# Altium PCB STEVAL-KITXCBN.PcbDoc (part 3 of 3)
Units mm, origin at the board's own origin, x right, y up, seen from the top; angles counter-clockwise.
Board outline 110 x 100 mm, 4 copper layers (Top Layer, GND, PWR, Bottom Layer), stack 1.53 mm thick; 227 components, 137 nets, 699 pads, 698 vias.
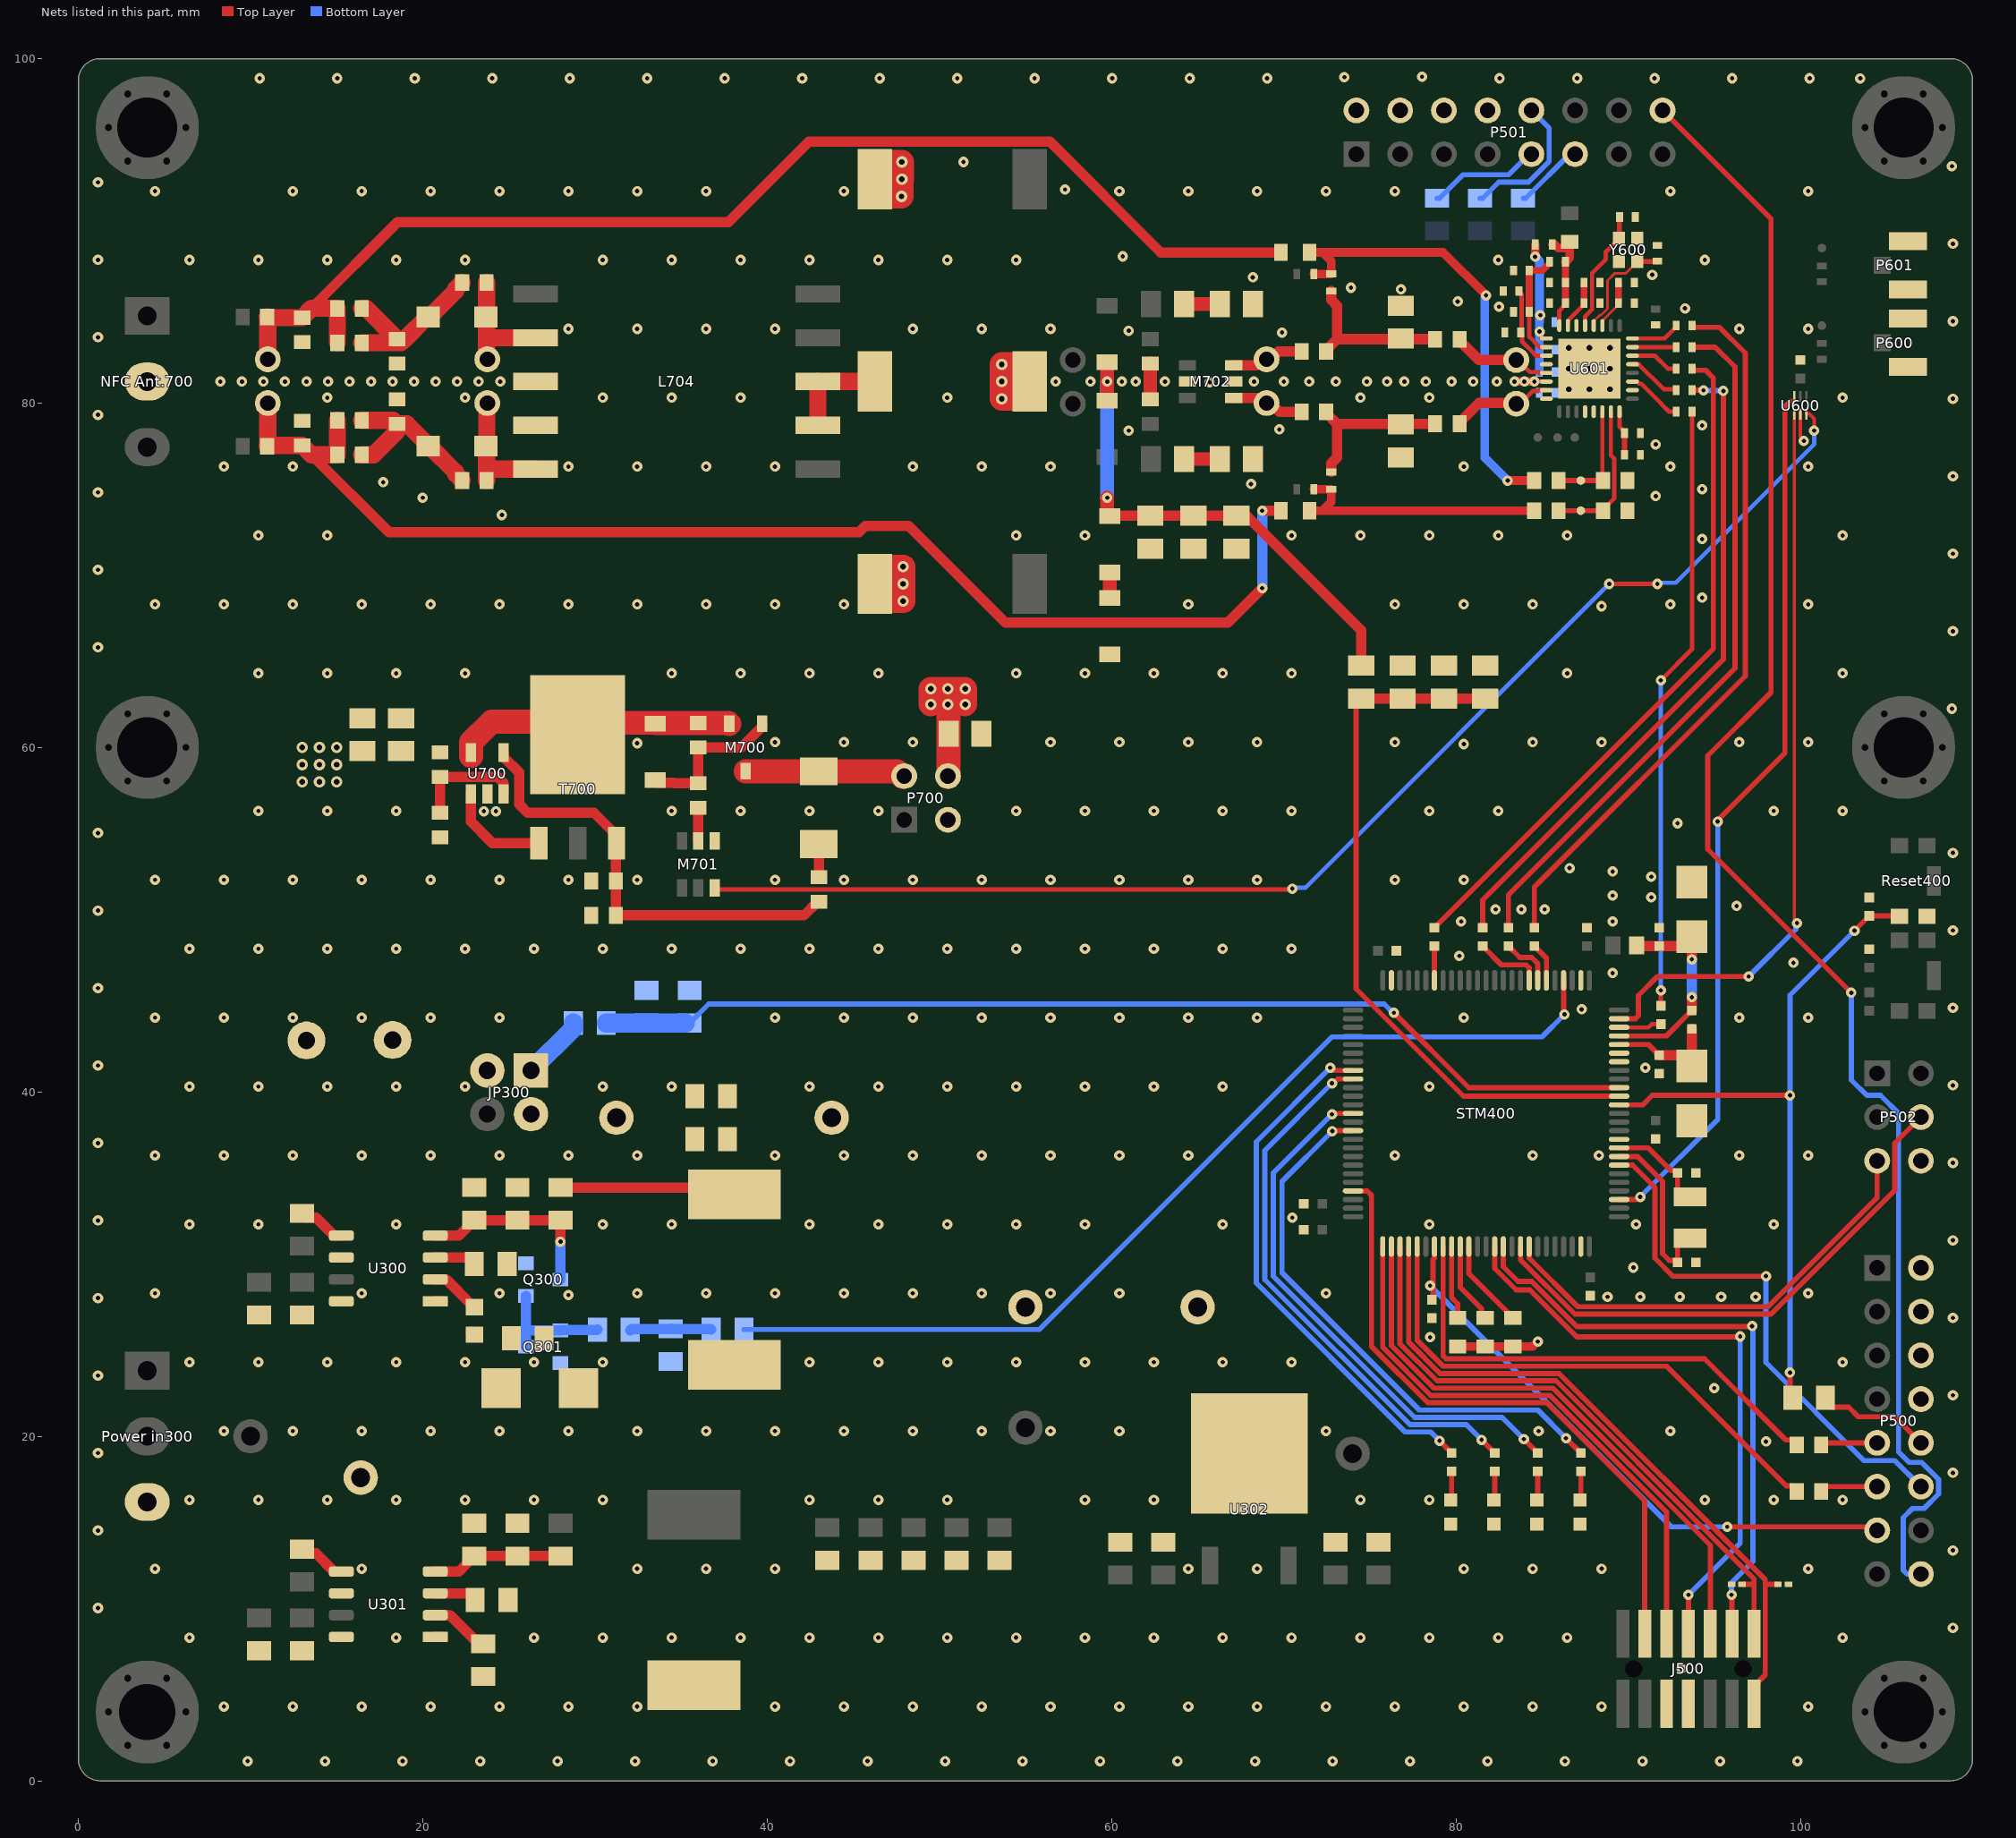
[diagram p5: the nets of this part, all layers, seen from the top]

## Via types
v1: diameter 0.6, hole 0.25, Top Layer to Bottom Layer, 566 vias
v2: diameter 0.66, hole 0.33, Top Layer to Bottom Layer, 94 vias
v3: diameter 0.6, hole 0.25, Top Layer to Bottom Layer, tented both sides, 38 vias

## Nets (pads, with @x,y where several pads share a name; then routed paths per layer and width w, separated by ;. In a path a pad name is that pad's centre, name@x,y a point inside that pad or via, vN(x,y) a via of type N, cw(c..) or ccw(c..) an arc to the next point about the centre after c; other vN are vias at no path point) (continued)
GND: "NFC Ant.700.2" "Power in300.3" C300.2 C301.1 C303.1 C304.1 C305.1 C306.1 C307.2 C308.2 C309.2 C311.2 C312.1 C313.2 C314.1 C315.1 C316.1 C317.1 C318.1 C319.2 C320.1 C321.2 C322.2 C323.1 C400.2 C402.2 C403.1 C404.2 C405.2 C406.2 C407.2 C408.1 C409.1 C410.1 C411.1 C412.1 C413.1 C600.1 C601.2 C602.2 C603.1 C608.2 C609.2 C610.2 C611.2 C612.2 C613.2 C618.2 C619.2 C620.2 C621.2 C622.2 C623.2 C624.2 C625.2 C626.2 C627.2 C628.2 C629.2 C700.2 C701.2 C702.2 C703.2 C704.2 C707.2 C708.1 C709.2 C710.2 C712.2 C713.2 C714.1 C715.1 D500.A D501.A D705.2 J400.1 J401.1 J402.1 J500.5 J500.7 L704.8 L704.9 LD401.1 LD402.1 LD403.1 LD404.1 M701.4 M702.2 M702.5 P500.2 P500.4 P500.6 P500.8 P501.2 P501.4 P501.6 P501.8 P502.6 P600.2 P600.3 P601.2 P601.3 Q300.2 Q301.2 R301.1 R305.1 R309.1 R400.1 R401.1 R610.2 R611.1 R705.2 R706.2 R707.2 R708.2 R711.2 Reset400.1 STM400.10 STM400.19 STM400.20 STM400.27 STM400.49 STM400.99 TP300.1 TP301.1 TP302.1 TP303.1 U300.6 U300.8 U301.6 U301.8 U302.2 U600.2 U601.6 U601.12 U601.16 U601.20 U601.21 U601.26 U601.33 U700.2 Y600.2 Y600.4 | length 6.6
  Top Layer w0.2: U600.2@100,79.53 100,78.081 100.2,77.881 v1(100.2,77.8)
  Top Layer w0.5: J400.1@80.1,25.218 J401.1@81.7,25.218 J402.1@83.3,25.218 84.468,25.218 v1(84.75,25.5)
  other v1: 9.832,1.143 14.332,1.143 18.832,1.143 23.332,1.143 27.832,1.143 32.332,1.143 36.832,1.143 41.332,1.143 45.832,1.143 50.332,1.143 54.832,1.143 59.332,1.143 63.832,1.143 68.332,1.143 72.832,1.143 77.332,1.143 81.832,1.143 86.332,1.143 90.832,1.143 95.332,1.143 99.832,1.143 8.456,4.31 12.456,4.31 16.456,4.31 20.456,4.31 24.456,4.31 28.456,4.31 32.456,4.31 40.456,4.31 44.456,4.31 48.456,4.31 52.456,4.31 56.456,4.31 60.456,4.31 64.456,4.31 68.456,4.31 72.456,4.31 76.456,4.31 80.456,4.31 84.456,4.31 88.456,4.31 100.456,4.31 93.1,6.5 6.456,8.31 18.456,8.31 26.456,8.31 30.456,8.31 34.456,8.31 38.456,8.31 42.456,8.31 46.456,8.31 50.456,8.31 54.456,8.31 58.456,8.31 62.456,8.31 66.456,8.31 70.456,8.31 74.456,8.31 78.456,8.31 82.456,8.31 86.456,8.31 102.456,8.31 108.857,8.88 1.143,10.031 4.456,12.31 16.456,12.31 32.456,12.31 36.456,12.31 40.456,12.31 64.456,12.31 68.456,12.31 80.456,12.31 84.456,12.31 88.456,12.31 100.456,12.31 108.857,13.38 1.143,14.531 6.456,16.31 10.456,16.31 14.456,16.31 18.456,16.31 22.456,16.31 26.456,16.31 30.456,16.31 42.456,16.31 46.456,16.31 50.456,16.31 58.456,16.31 62.456,16.31 74.456,16.31 78.456,16.31 94.456,16.31 98.456,16.31 102.456,16.31 108.857,17.88 1.143,19.031 98,19.7 8.456,20.31 12.456,20.31 16.456,20.31 20.456,20.31 24.456,20.31 28.456,20.31 32.456,20.31 36.456,20.31 40.456,20.31 44.456,20.31 48.456,20.31 52.456,20.31 56.456,20.31 60.456,20.31 72.456,20.31 84.8,20.31 92.456,20.31 108.857,22.38 95,22.8 1.143,23.531 6.456,24.31 10.456,24.31 14.456,24.31 18.456,24.31 22.456,24.31 26.456,24.31 30.456,24.31 42.456,24.31 46.456,24.31 50.456,24.31 54.456,24.31 58.456,24.31 62.456,24.31 66.456,24.31 70.456,24.31 102.456,24.31 78.5,25.75 108.857,26.88 1.143,28.031 88.8,28.1 90.7,28.1 93,28.1 95.4,28.1 97.4,28.1 28.456,28.2 4.456,28.31 16.456,28.31 24.456,28.31 32.456,28.31 36.456,28.31 40.456,28.31 44.456,28.31 48.456,28.31 52.456,28.31 56.456,28.31 60.456,28.31 72.456,28.31 100.456,28.31 90.3,29.8 108.857,31.38 6.456,32.31 10.456,32.31 18.456,32.31 30.456,32.31 34.456,32.31 42.456,32.31 46.456,32.31 50.456,32.31 54.456,32.31 58.456,32.31 66.456,32.31 78.456,32.31 90.456,32.31 98.456,32.31 1.143,32.531 70.5,32.7 108.857,35.88 4.456,36.31 8.456,36.31 12.456,36.31 16.456,36.31 20.456,36.31 24.456,36.31 28.456,36.31 32.456,36.31 40.456,36.31 44.456,36.31 48.456,36.31 52.456,36.31 56.456,36.31 60.456,36.31 64.456,36.31 76.456,36.31 84.456,36.31 88.3,36.31 96.456,36.31 100.456,36.31 1.143,37.031 6.456,40.31 10.456,40.31 14.456,40.31 18.456,40.31 22.456,40.31 30.456,40.31 34.456,40.31 42.456,40.31 46.456,40.31 50.456,40.31 54.456,40.31 58.456,40.31 62.456,40.31 66.456,40.31 78.456,40.31 108.857,40.38 91,41.4 1.143,41.531 4.456,44.31 8.456,44.31 12.456,44.31 16.456,44.31 20.456,44.31 24.456,44.31 40.456,44.31 44.456,44.31 48.456,44.31 52.456,44.31 56.456,44.31 60.456,44.31 64.456,44.31 68.456,44.31 80.456,44.31 96.456,44.31 100.456,44.31 87.3,44.8 108.857,44.88 1.143,46.031 89.1,46.9 99.6,47.5 80.2,47.9 6.456,48.31 10.456,48.31 14.456,48.31 18.456,48.31 22.456,48.31 26.456,48.31 30.456,48.31 34.456,48.31 38.456,48.31 42.456,48.31 46.456,48.31 50.456,48.31 54.456,48.31 58.456,48.31 62.456,48.31 66.456,48.31 70.456,48.31 108.857,49.38 80.3,49.9 89.1,49.9 1.143,50.531 82.3,50.6 83.8,50.6 85.15,50.6 96.3,50.8 91.34,51.3 89.1,51.4 4.456,52.31 8.456,52.31 12.456,52.31 16.456,52.31 20.456,52.31 24.456,52.31 28.456,52.31 32.456,52.31 40.456,52.31 44.456,52.31 48.456,52.31 52.456,52.31 56.456,52.31 60.456,52.31 64.456,52.31 68.456,52.31 76.456,52.31 80.456,52.31 91.34,52.5 89.1,52.8 86.6,53 108.857,53.88 1.143,55.031 92.871,55.601 23.55,56.3 24.25,56.3 10.456,56.31 14.456,56.31 18.456,56.31 34.456,56.31 38.456,56.31 42.456,56.31 46.456,56.31 54.456,56.31 58.456,56.31 62.456,56.31 66.456,56.31 70.456,56.31 78.456,56.31 82.456,56.31 98.456,56.31 102.456,56.31 80.456,60.2 32.456,60.25 40.456,60.31 44.456,60.31 48.456,60.31 56.456,60.31 60.456,60.31 64.456,60.31 68.456,60.31 76.456,60.31 84.456,60.31 88.456,60.31 96.456,60.31 100.456,60.31 108.799,62.251 10.456,64.31 14.456,64.31 18.456,64.31 22.456,64.31 34.456,64.31 38.456,64.31 42.456,64.31 46.456,64.31 54.456,64.31 58.456,64.31 62.456,64.31 66.456,64.31 70.456,64.31 86.456,64.31 102.456,64.31 1.143,65.817 108.857,66.751 88.456,68.2 4.456,68.31 8.456,68.31 12.456,68.31 16.456,68.31 20.456,68.31 24.456,68.31 28.456,68.31 32.456,68.31 36.456,68.31 40.456,68.31 44.456,68.31 64.456,68.31 76.456,68.31 80.456,68.31 84.456,68.31 92.456,68.31 100.456,68.31 94.3,68.7 1.143,70.317 108.857,71.251 94.3,72.1 10.456,72.31 14.456,72.31 54.456,72.31 58.456,72.31 70.456,72.31 74.456,72.31 78.456,72.31 82.456,72.31 86.456,72.31 102.456,72.31 24.6,73.5 20,74.5 91.6,74.6 1.143,74.817 94.3,75 68.1,75.3 17.7,75.4 108.857,75.751 8.456,76.31 12.456,76.31 28.456,76.31 32.456,76.31 36.456,76.31 40.456,76.31 48.456,76.31 52.456,76.31 56.456,76.31 80.456,76.31 92.456,76.31 100.456,76.31 91.6,77.6 69.741,78.471 94.3,78.7 1.143,79.317 108.857,80.251 14.456,80.31 22.456,80.31 30.456,80.31 34.456,80.31 38.456,80.31 50.456,80.31 74.456,80.31 78.456,80.31 102.456,80.31 65.7,81.2 1.143,83.817 69.9,84.1 28.456,84.31 32.456,84.31 36.456,84.31 40.456,84.31 48.456,84.31 52.456,84.31 56.456,84.31 96.456,84.31 100.456,84.31 108.857,84.751 93.3,85.5 82.5,85.6 80.1,85.9 76.8,86.6 73.9,86.7 68.2,87.3 91.4,87.45 1.143,88.317 6.456,88.31 10.456,88.31 14.456,88.31 18.456,88.31 22.456,88.31 30.456,88.31 34.456,88.31 38.456,88.31 42.456,88.31 46.456,88.31 50.456,88.31 54.456,88.31 82.456,88.31 94.456,88.31 60.654,88.518 108.857,89.251 4.456,92.31 12.456,92.31 16.456,92.31 20.456,92.31 24.456,92.31 28.456,92.31 32.456,92.31 36.456,92.31 44.456,92.31 60.456,92.31 64.456,92.31 68.456,92.31 72.456,92.31 76.456,92.31 92.456,92.31 100.456,92.31 57.3,92.4 1.143,92.817 108.799,93.751 51.4,94 10.537,98.857 15.037,98.857 19.537,98.857 24.037,98.857 28.537,98.857 33.037,98.857 37.537,98.857 42.037,98.857 46.537,98.857 51.037,98.857 55.537,98.857 60.037,98.857 64.537,98.857 69.037,98.857 82.537,98.857 87.037,98.857 91.537,98.857 96.037,98.857 100.537,98.857 103.473,98.854 73.52,98.919 78.037,98.945
  other v2: 86.55,80.8 87.75,80.8 88.95,80.8 86.55,82 87.75,82 88.95,82 86.55,83.2 87.75,83.2 88.95,83.2
  other v3: 61,78.4 8.25,81.25 9.5,81.25 10.75,81.25 12,81.25 13.25,81.25 14.5,81.25 15.75,81.25 17,81.25 18.25,81.25 19.5,81.25 20.75,81.25 22,81.25 23.25,81.25 24.5,81.25 56.75,81.25 58.775,81.25 60.6,81.25 61.4,81.25 63.1,81.25 68.275,81.25 70,81.25 71.475,81.25 73.025,81.25 74.825,81.25 76,81.25 77,81.25 78.25,81.25 79.75,81.25 81,81.25 82.375,81.25 61,84.2
IGBT_drive: P500.16 P501.16 | length 97.7
  Top Layer w0.3: P501.16@92,96.995 98.3,90.695 98.3,63.199 94.625,59.524 94.625,54.094 v1(102.959,45.759)
  Bottom Layer w0.3: v1(102.959,45.759) 102.959,40.692 103.852,39.799 104.65,39.799 105.7,38.75 105.7,19.1 106.313,18.487 107.042,18.487 108.025,17.505 108.025,16.655 107.18,15.81 106.51,15.81 105.975,15.275 105.975,12.225 106.2,12 P500.16@107,12
INTR: R402.1 R603.2 | length 35.2
  Top Layer w0.25: R402.1@91.9,45 v1(91.9,45.9) ; v1(91.9,63.9) 93.707,65.707 R603.2@93.707,79.5
  Bottom Layer w0.25: v1(91.9,45.9) v1(91.9,63.9)
LED1: R411.1 STM400.58 | length 31.1
  Top Layer w0.3: v1(72.7,41.4) 72.781,41.4 72.931,41.25 STM400.58@74.025,41.25 ; v1(79.042,19.742) R411.1@79.75,19.033
  Bottom Layer w0.3: v1(72.7,41.4) 68.4,37.1 68.4,28.9 77.05,20.25 78.533,20.25 v1(79.042,19.742)
LED2: R408.1 STM400.59 | length 31.9
  Top Layer w0.3: v1(72.8,40.5) 72.881,40.5 73.131,40.75 STM400.59@74.025,40.75 ; v1(81.492,19.792) R408.1@82.25,19.033
  Bottom Layer w0.3: v1(72.8,40.5) 68.9,36.6 68.9,29.1 77.325,20.675 80.608,20.675 v1(81.492,19.792)
LED3: R407.1 STM400.63 | length 31.7
  Top Layer w0.3: v1(72.8,38.7) 72.85,38.75 STM400.63@74.025,38.75 ; v1(83.942,19.842) R407.1@84.75,19.033
  Bottom Layer w0.3: v1(72.8,38.7) 69.4,35.3 69.4,29.297 77.597,21.1 82.683,21.1 v1(83.942,19.842)
LED4: R406.1 STM400.65 | length 32.3
  Top Layer w0.3: v1(72.819,37.719) 72.85,37.75 STM400.65@74.025,37.75 ; v1(86.392,19.892) R406.1@87.25,19.033
  Bottom Layer w0.3: v1(72.819,37.719) 69.9,34.8 69.9,29.5 77.875,21.525 84.758,21.525 v1(86.392,19.892)
MISO: R403.1 R607.2 | length 42.2
  Top Layer w0.3: R403.1@84.55,49.533 84.55,51.897 96.8,64.147 96.8,82.9 95.3,84.4 93.757,84.4 93.707,84.45 R607.2@93.707,84.5
MOSI: R404.1 R606.2 | length 41
  Top Layer w0.3: R404.1@83.05,49.533 83.05,51.448 96.2,64.598 96.2,82.1 95.05,83.25 R606.2@93.707,83.25
NetC302_1: C302.1 U300.2 | length 2.9
  Top Layer w0.6: U300.2@20.725,29.115 21.36,29.115 22.8,27.675 22.825,27.675 C302.1@23,27.5
NetC302_2: C302.2 D300.1 R310.2 U300.1 | length 0.7
  Top Layer w0.6: U300.1@20.725,27.845 U300.1@21.15,27.845 ; C302.2@22.8,26.075 22.825,26.075 C302.2@23,25.9
NetC307_1: C307.1 U300.3 | length 2.5
  Top Layer w0.6: U300.3@20.725,30.385 22.75,30.385 23,30.135 C307.1@23,30
NetC308_1: C308.1 Q300.3 R303.1 R305.2 U300.4 | length 11.2
  Top Layer w0.6: U300.4@20.725,31.655 22.105,31.655 22.6,32.15 22.6,32.3 22.85,32.55 C308.1@23,32.55 R305.2@25.5,32.55 R303.1@28,32.55 v1(28,31.3)
  Bottom Layer w0.6: Q300.3@28,29.1 v1(28,31.3)
NetC309_1: C309.1 R304.2 R306.2 | length 4.8
  Bottom Layer w0.6: R306.2@32.05,26.15 32.125,26.225 34.375,26.225 C309.1@34.4,26.25 34.425,26.225 36.725,26.225 R304.2@36.75,26.2
NetC310_1: C310.1 L301.1 U301.1 | length 0.4
  Top Layer w0.6: U301.1@20.725,8.345 U301.1@21.15,8.345
NetC310_2: C310.2 U301.2 | length 3.5
  Top Layer w0.6: U301.2@20.725,9.615 21.485,9.615 21.5,9.6 21.6,9.6 23,8.2 23.25,8.2 C310.2@23.5,7.95
NetC313_1: C313.1 U301.3 | length 2.5
  Top Layer w0.5: C313.1@22.75,10.885 23.05,10.585 C313.1@23.05,10.5
  Top Layer w0.6: U301.3@20.725,10.885 C313.1@22.75,10.885
NetC319_1: C319.1 R308.1 R309.2 U301.4 | length 7.9
  Top Layer w0.6: U301.4@20.725,12.155 22.105,12.155 22.6,12.65 22.6,12.8 C319.1@22.85,13.05 ; C319.1@23,13.05 C319.1@22.85,13.05 ; R308.1@28,13.05 R309.2@25.5,13.05 C319.1@22.85,13.05
NetC601_1: C601.1 C602.1 U601.24 | length 2.6
  Top Layer w0.25: U601.24@89.5,79.5 89.5,78.622 89.793,78.329 C601.1@89.793,78.25
  Top Layer w0.3: C602.1@89.793,77 C601.1@89.793,78.25
NetC604_2: C604.2 J602.2 J603.1 J604.2 | length 15.4
  Top Layer w0.5: J603.1@71.5,73.75 72.25,73.75 ; J602.2@71.75,75 72.175,75 ; 72.225,75 J604.2@72.75,75 72.75,74.25 72.25,73.75 ; C604.2@84.539,73.75 72.25,73.75
NetC605_2: C605.2 J604.1 R602.1 R610.1 | length 9.6
  Top Layer w0.6: R602.1@72.461,79.5 72.461,79.424 73.096,78.789 ; J604.1@72.75,76 72.75,76.501 73.096,76.847 73.096,78.789 ; C605.2@78.789,78.789 73.096,78.789
NetC616_2: C616.2 J607.2 R608.1 R611.2 | length 9.6
  Top Layer w0.6: R608.1@72.461,83 72.461,83.076 73.096,83.711 ; J607.2@72.75,86.5 72.75,85.999 73.096,85.653 73.096,83.711 ; C616.2@78.789,83.711 73.096,83.711
NetC617_1: C617.1 J607.1 J608.2 J609.1 | length 26.6
  Top Layer w0.5: J609.1@71.5,88.75 72.25,88.75 ; J608.2@71.75,87.5 72.475,87.5 J607.1@72.75,87.5 72.75,88.25 72.25,88.75 ; v1(81.75,86.25) 79.25,88.75 72.25,88.75 ; v1(83,75.5) C617.1@84.539,75.5
  Bottom Layer w0.5: v1(81.75,86.25) 81.75,86.223 81.675,86.148 81.675,76.825 v1(83,75.5)
NetC628_1: C628.1 U601.4 Y600.3 | length 6.4
  Top Layer w0.15: U601.4@88,84.5 88,84.75 88.37,85.12 88.439,85.12 88.799,85.48 88.799,87.119 89.203,87.522 89.847,87.522 90.525,88.2 Y600.3@90.525,88.225
  Top Layer w0.2: U601.4@88,84.5 U601.4@88.01,84.51
  Top Layer w0.3: Y600.3@90.525,88.225 C628.1@91.603,88.225
  Top Layer w0.4: C628.1@91.621,88.243 C628.1@91.7,88.243
NetC629_1: C629.1 U601.5 Y600.1 | length 7.1
  Top Layer w0.25: U601.5@87.5,84.5 87.5,85.024 87.907,85.431 87.907,87.554 88.7,88.347 88.7,88.777 89.473,89.55 Y600.1@89.473,89.575 Y600.1@89.487,89.588 ; C629.1@89.487,90.787 C629.1@89.5,90.8
  Top Layer w0.3: Y600.1@89.487,89.588 C629.1@89.487,90.787
NetC700_1: C700.1 L700.2 L701.2 L702.2 P700.4 | length 26.1
  Top Layer w1.4: L700.2@46.25,69.5 46.25,70.2 46.55,70.5 v2(47.9,70.5) v2(47.9,69.5) v2(47.9,68.5) L700.2@46.55,68.5 ; L701.2@46.55,92.7 L701.2@46.25,93 46.25,92.3 46.55,92 v2(47.8,92) 47.8,92.975 v2(47.825,93) v2(47.825,94) L701.2@46.575,94 ; v2(49.5,62.5) v2(49.5,63.4) v2(50.5,63.4) v2(51.5,63.4) v2(51.5,62.5) ; P700.4@50.54,58.3 v2@50.54,62.5 ; L702.2@54.975,80.25 v2(53.625,80.25) v2(53.625,81.25) v2(53.625,82.25) L702.2@54.975,82.25 ; L702.2@55.25,80.5 L702.2@55.25,81.25 L702.2@55.25,82
  other v2: 50.5,62.5
NetC705_2: C705.2 C706.1 | length 2.1
  Top Layer w0.8: C706.1@62.25,80.211 C705.2@62.25,82.289
NetC707_1: C707.1 R703.2 R707.1 R708.1 STM400.15 | length 41.9
  Top Layer w0.3: R703.2@74.2,62.847 74.2,45.987 80.437,39.75 STM400.15@89.475,39.75
  Top Layer w0.6: R703.2@74.5,62.847 R707.1@76.9,62.847 C707.1@79.3,62.847 R708.1@81.7,62.847
NetC708_2: C708.2 R704.2 R711.1 T700.3 U700.4 | length 26.5
  Top Layer w0.6: U700.4@24.7,59.7 24.7,59.45 25.6,58.55 25.6,56.7 26.1,56.2 29.95,56.2 31.25,54.9 T700.3@31.25,54.45 31.211,54.411 C708.2@31.211,52.25 R711.1@31.211,50.25 42.135,50.25 42.924,51.039 R704.2@43,51.039
NetC709_1: C709.1 R709.2 | length 2.1
  Top Layer w0.8: R709.2@64.203,85.75 C709.1@66.298,85.75
NetC710_1: C710.1 R710.2 | length 2.1
  Top Layer w0.8: R710.2@64.203,76.75 C710.1@66.298,76.75
NetC711_1: C711.1 C712.1 L703.2 R712.2 R713.1 | length 10.5
  Top Layer w1: R713.1@16.461,77 17.15,77 18.5,78.35 C712.1@18.5,78.789 ; C711.1@16.461,79 16.464,78.997 18.291,78.997 C712.1@18.5,78.789 ; R712.2@22.289,75.5 21.914,75.875 21.914,75.986 20.4,77.5 20.25,77.5 20.15,77.6 20.15,77.722 19.083,78.789 C712.1@18.5,78.789
NetC714_2: C714.2 C716.1 L705.2 R716.2 R717.1 | length 10.6
  Top Layer w1: C716.1@16.461,83.5 18.75,83.5 C714.2@18.961,83.711 ; R717.1@16.461,85.5 16.711,85.5 C714.2@18.5,83.711 C714.2@18.961,83.711 ; R716.2@22.289,87 21.914,86.625 21.914,86.514 20.4,85 L705.2@20.325,85 20.25,85 C714.2@18.961,83.711
NetD300_2: D300.2 L300.1 R310.1
NetD700_2: D700.2 M700.1 R701.2 R702.1 | length 9
  Top Layer w0.6: D700.2@33.5,58.115 33.655,57.96 34.58,57.96 34.617,57.922 R702.1@36,57.922 R701.2@36,60 38.5,60 39.7,61.2 M700.1@39.7,61.375
NetD701_1: D701.1 R704.1 | length 1.9
  Top Layer w0.6: R704.1@43,52.461 D701.1@43,54.39
NetD701_2: D701.2 M700.3 P700.2 | length 9.2
  Top Layer w1.4: M700.3@38.75,58.625 47.535,58.625 P700.2@47.86,58.3
NetD704_2: D704.2 D705.1 | length 1.5
  Top Layer w0.8: D705.1@59.9,68.685 D704.2@59.9,70.165
NetJ701_1: J701.1 L703.1 L704.10 R712.1 | length 7.4
  Top Layer w1: R712.1@23.711,75.5 23.711,76.2 ; J701.1@23.75,80 23.713,79.962 23.713,77.538 L703.1@23.675,77.5 23.711,77.464 23.711,76.2 ; L704.10@26.55,76.17 23.741,76.17 23.711,76.2
NetJ701_2: J701.2 L704.7 L705.1 R716.1 | length 7.3
  Top Layer w1: R716.1@23.711,87 23.711,83.8 ; J701.2@23.75,82.54 23.711,82.579 23.711,83.8 ; L704.7@26.55,83.79 23.721,83.79 23.711,83.8
NetLD401_2: LD401.2 R411.2 | length 1.8
  Top Layer w0.3: LD401.2@79.75,16.198 R411.2@79.75,17.967
NetLD402_2: LD402.2 R408.2 | length 1.8
  Top Layer w0.3: LD402.2@82.25,16.198 R408.2@82.25,17.967
NetLD403_2: LD403.2 R407.2 | length 1.8
  Top Layer w0.3: LD403.2@84.75,16.198 R407.2@84.75,17.967
NetLD404_2: LD404.2 R406.2 | length 1.8
  Top Layer w0.3: LD404.2@87.25,16.198 R406.2@87.25,17.967
NetM701_1: M701.5 R702.2 | length 1.9
  Top Layer w0.6: M701.5@36,54.576 R702.2@36,56.5
NetP500_9: P500.9 R500.2 | length 3.1
  Top Layer w0.3: R500.2@101.45,19.5 101.57,19.62 P500.9@104.46,19.62
NetP500_10: P500.10 R501.1 | length 6.7
  Top Layer w0.3: R501.1@101.45,22.25 101.45,22.1 101.85,21.7 102.8,21.7 103.365,21.135 105.485,21.135 P500.10@107,19.62
NetP500_11: P500.11 R502.2 | length 3.4
  Top Layer w0.3: R502.2@101.211,16.8 101.211,16.824 101.468,17.08 P500.11@104.46,17.08
NetP501_9: P501.9 R503.2 | length 6.5
  Bottom Layer w0.3: R503.2@78.9,91.9 79.05,91.9 80.413,93.263 83.062,93.263 84.254,94.455 P501.9@84.38,94.455
NetP501_10: P501.10 R504.1 | length 8.3
  Bottom Layer w0.3: R504.1@81.4,91.9 81.55,91.9 82.488,92.838 83.199,92.838 84.212,92.838 85.405,94.03 85.405,95.97 84.496,96.879 P501.10@84.38,96.995
NetP501_11: P501.11 R505.2 | length 4.2
  Bottom Layer w0.3: R505.2@83.9,91.9 84.05,91.9 86.605,94.455 P501.11@86.92,94.455 ; P501.11@86.875,94.34 P501.11@87.035,94.34
NetQ300_1: Q300.1 Q301.1 Q301.3 R306.1 | length 7.1
  Bottom Layer w0.6: Q301.3@26,25.2 26,26.2 ; Q300.1@26,28.15 26,26.2 ; R306.1@30.15,26.2 30.125,26.175 28.025,26.175 Q301.1@28,26.15 26.05,26.15 26,26.2
NetR302_1: R302.1 U300.5 | length 2.8
  Top Layer w0.6: R302.1@13,32.95 13.25,32.7 13.805,32.7 14.85,31.655 U300.5@15.275,31.655
NetR307_1: R307.1 U301.5 | length 2.8
  Top Layer w0.5: U301.5@14.85,12.155 U301.5@15.275,12.155
  Top Layer w0.6: R307.1@13,13.45 13.25,13.2 13.805,13.2 U301.5@14.85,12.155
NetR402_2: R402.2 STM400.23 | length 2.5
  Top Layer w0.25: STM400.23@89.475,43.75 89.485,43.74 91.174,43.74 91.367,43.933 R402.2@91.9,43.933
NetR403_2: R403.2 STM400.31 | length 2.3
  Top Layer w0.3: R403.2@84.55,48.467 85.25,47.767 STM400.31@85.25,46.475
NetR404_2: R404.2 STM400.32 | length 3.1
  Top Layer w0.3: R404.2@83.05,48.467 83.709,47.807 84.393,47.807 84.75,47.45 STM400.32@84.75,46.475
NetR405_2: R405.2 STM400.33 | length 4
  Top Layer w0.3: R405.2@81.55,48.467 82.634,47.382 84.074,47.382 84.25,47.206 STM400.33@84.25,46.475
NetR410_2: R410.2 STM400.44 | length 2
  Top Layer w0.3: STM400.44@78.75,46.475 R410.2@78.75,48.467
NetR603_1: R603.1 U601.27 | length 3.3
  Top Layer w0.25: U601.27@90.25,81.25 90.5,81.25 90.625,81.125 90.753,81.125 91.95,79.928 91.95,79.916 92.364,79.502 92.718,79.502 92.719,79.5 R603.1@92.793,79.5
NetR604_1: R604.1 U601.29 | length 3.2
  Top Layer w0.25: U601.29@90.25,82.25 90.616,82.25 92.061,80.805 92.738,80.805 R604.1@92.793,80.75
NetR605_1: R605.1 U601.30 | length 2.9
  Top Layer w0.25: U601.30@90.25,82.75 91.55,82.75 92.3,82 R605.1@92.793,82
NetR606_1: R606.1 U601.31 | length 2.5
  Top Layer w0.25: U601.31@90.25,83.25 R606.1@92.793,83.25
NetR607_1: R607.1 U601.32 | length 2.9
  Top Layer w0.25: U601.32@90.25,83.75 92.122,83.75 92.793,84.421 R607.1@92.793,84.5
NetR700_2: R700.2 R706.1 U700.3 | length 6.6
  Top Layer w0.6: R706.1@21,56.211 R700.2@21,58.289 24.349,58.289 24.7,57.937 U700.3@24.7,57.3
NetSTM400_3: STM400.3 U600.6 | length 51.4
  Top Layer w0.2: 99.4,80.1 99.65,80.1 U600.6@99.65,80.2
  Top Layer w0.3: STM400.3@89.475,33.75 90.469,33.75 90.619,33.9 v1(90.7,33.9) ; v1(95.2,55.7) 95.2,55.781 99.1,59.681 99.1,79.8 99.4,80.1
  Bottom Layer w0.3: v1(90.7,33.9) 95.2,38.4 v1(95.2,55.7)
NetSTM400_24: STM400.24 U600.1 | length 43.3
  Top Layer w0.2: U600.1@99.65,79.53 99.65,50.058 99.8,49.908 v1(99.8,49.8)
  Top Layer w0.3: STM400.24@89.475,44.25 90.424,44.25 90.6,44.426 90.6,45.6 91.7,46.7 v1(97,46.7)
  Bottom Layer w0.3: v1(97,46.7) 99.743,49.443 99.743,49.743 v1(99.8,49.8)
NetT700_1: T700.1 U700.1 | length 6.1
  Top Layer w0.6: U700.1@22.8,57.3 22.8,55.7 24.05,54.45 T700.1@26.75,54.45
NFC_Ready: P500.13 R401.2 STM400.82 | length 35.2
  Top Layer w0.3: v1(78.5,28.75) v1@78.675,28.75 ; R401.2@78.6,27.933 78.675,28.008 v1@78.675,28.75 ; STM400.82@78.75,31.025 78.75,30.35 78.675,30.275 v1@78.675,28.75 ; v1(95.75,14.75) 104.25,14.75 P500.13@104.46,14.54
  Bottom Layer w0.3: v1(78.5,28.75) 92.5,14.75 v1(95.75,14.75)
NFC_Reset: C403.2 R501.2 Reset400.2 STM400.14 | length 41.7
  Top Layer w0.3: STM400.14@89.475,39.25 90.85,39.25 91.4,39.8 v1(99.4,39.8) ; R501.2@99.3,22.4 99.4,22.5 v1(99.4,23.7) ; v1(103.142,49.358) C403.2@104,50.217 105.733,50.217 Reset400.2@105.75,50.2
  Bottom Layer w0.3: v1(99.4,23.7) v1(99.4,39.8) 99.4,45.617 v1(103.142,49.358)
NFC_Uart_Rx: R500.1 STM400.83 | length 29
  Top Layer w0.3: STM400.83@79.25,31.025 79.25,24.676 79.426,24.5 94.438,24.5 99.151,19.787 99.532,19.787 99.789,19.531 R500.1@99.789,19.5
NFC_Uart_Tx: R502.1 STM400.80 | length 31.1
  Top Layer w0.3: STM400.80@77.75,31.025 77.75,25.575 79.25,24.075 92.225,24.075 99.182,17.118 99.532,17.118 99.55,17.101 R502.1@99.55,16.75
NFC_Wake_Up: P500.12 STM400.7 | length 30.6
  Top Layer w0.3: STM400.7@89.475,35.75 90.25,35.75 91.551,34.449 91.551,30.349 92.6,29.3 v1(98,29.3)
  Bottom Layer w0.3: v1(98,29.3) 98,24.287 103.692,18.595 105.485,18.595 P500.12@107,17.08
PA1: J606.2 M702.3 R608.2 | length 4.3
  Top Layer w0.6: M702.3@67.1,82.2 68.416,82.2 68.756,82.54 J606.2@69,82.54 69.244,82.54 69.704,83 R608.2@71.039,83
PA2: J606.1 M702.1 R602.2 | length 4.3
  Top Layer w0.6: M702.1@67.1,80.3 68.456,80.3 68.756,80 J606.1@69,80 69.244,80 69.744,79.5 R602.2@71.039,79.5
PC14: C400.1 STM400.8 X400.2 | length 10.3
  Top Layer w0.3: STM400.8@89.475,36.25 90.55,36.25 92,34.8 92,30.6 92.386,30.214 92.752,30.214 C400.1@92.867,30.1 92.867,31.1 93.267,31.5 X400.2@93.6,31.5
PC15: C402.1 STM400.9 X400.1 | length 5.9
  Top Layer w0.3: STM400.9@89.475,36.75 91.169,36.75 92.489,35.429 92.737,35.429 C402.1@92.867,35.3 92.867,34.3 93.267,33.9 X400.1@93.6,33.9
RFI1: C617.2 C625.1 TP601.1 U601.22 | length 6.6
  Top Layer w0.25: U601.22@88.5,79.5 88.5,75.539 C625.1@88.539,75.5
  Top Layer w0.3: C617.2@85.961,75.5 TP601.1@87.25,75.5 C625.1@88.539,75.5
RFI1_E: C715.2 C716.2 J609.2 J702.2 R715.1 R717.2 | length 71.7
  Top Layer w0.6: 13.539,85.5 18.539,90.5 37.75,90.5 42.425,95.175 56.426,95.175 62.851,88.75 J609.2@69.836,88.75
  Top Layer w1: R715.1@10.961,85 R715.1@11,84.961 ; J702.2@11,82.54 R715.1@11,84.961 ; C716.2@15.039,83.5 R717.2@15.039,85.5 13.539,85.5 C715.2@13,84.961 R715.1@11,84.961
RFI2: C603.2 C604.1 TP600.1 U601.23 | length 8.7
  Top Layer w0.25: C603.2@88.539,73.75 88.539,73.826 89.195,74.483 89.195,76.769 89,76.964 U601.23@89,79.5
  Top Layer w0.3: C604.1@85.961,73.75 TP600.1@87.25,73.75 C603.2@88.539,73.75
RFI2_E: C711.2 C713.1 J603.2 J702.1 R713.2 R714.1 | length 74.8
  Top Layer w0.6: 13.539,77 18.039,72.5 45.338,72.5 45.713,72.875 48.208,72.875 53.833,67.25 66.75,67.25 v1(68.75,69.25) ; v1(68.75,73.75) J603.2@69.836,73.75
  Top Layer w1: R714.1@10.961,77.5 R714.1@11,77.539 ; J702.1@11,80 R714.1@11,77.539 ; C711.2@15.039,79 R713.2@15.039,77 13.539,77 C713.1@13,77.539 R714.1@11,77.539
  Bottom Layer w0.6: v1(68.75,69.25) v1(68.75,73.75)
RFO1: C616.1 J605.2 U601.13 | length 6
  Top Layer w0.25: J605.2@83.5,82.5 83.591,82.5 84.291,81.8 84.778,81.8 84.828,81.75 U601.13@85.241,81.75
  Top Layer w0.6: C616.1@80.211,83.776 C616.1@80.211,83.7 80.211,83.624 81.335,82.5 83.453,82.5 83.476,82.524 J605.2@83.5,82.5
RFO2: C605.1 J605.1 U601.15 | length 6
  Top Layer w0.25: J605.1@83.5,79.96 83.736,79.96 84.476,80.7 84.778,80.7 84.828,80.75 U601.15@85.25,80.75
  Top Layer w0.6: C605.1@80.211,78.624 C605.1@80.211,78.7 ; C605.1@80.211,78.8 80.211,78.876 81.335,80 83.4,80 83.47,79.93 J605.1@83.5,79.96
SCLK: R410.1 R605.2 | length 40.1
  Top Layer w0.3: R410.1@78.75,49.533 94.95,65.733 94.95,81.45 94.5,81.9 93.757,81.9 93.707,81.95 R605.2@93.707,82
SEN: R405.1 R604.2 | length 38.8
  Top Layer w0.3: R405.1@81.55,49.533 81.55,51.15 95.525,65.125 v1(95.525,80.7) ; R604.2@93.707,80.75 93.713,80.744 94.369,80.744 v1(94.375,80.737)
  Bottom Layer w0.3: v1(94.375,80.737) 94.394,80.719 95.506,80.719 v1(95.525,80.7)
Spare_GPIO: P502.5 STM400.93 | length 26.8
  Top Layer w0.3: STM400.93@84.25,31.025 84.25,30.349 87.074,27.525 98.126,27.525 104.46,33.859 P502.5@104.46,36
Spare_PWM: P502.4 STM400.92 | length 31.4
  Top Layer w0.3: STM400.92@83.75,31.025 83.75,30.248 86.898,27.1 98.302,27.1 105.485,34.283 105.485,37.025 106.811,38.351 P502.4@106.85,38.351
STLINK_UART_RX: D500.K J500.13 STM400.79 | length 40.2
  Top Layer w0.3: STM400.79@77.25,31.025 77.25,25.474 79.074,23.65 85.985,23.65 97.96,11.675 97.96,10.9 97.96,6.14 97.31,5.49 J500.13@97.31,4.465 ; 97.96,11.4 D500.K@98.7,11.4
STLINK_UART_TX: D501.K J500.14 STM400.78 | length 35.7
  Top Layer w0.3: STM400.78@76.75,31.025 76.75,25.373 78.898,23.225 85.809,23.225 95.195,13.839 97.31,11.724 97.31,10.9 J500.14@97.31,8.535 ; D501.K@96.7,11.4 97.31,11.4
SYS_JTCK_SWDCLK: J500.6 STM400.76 | length 32.2
  Top Layer w0.3: STM400.76@75.75,31.025 75.75,25.171 78.546,22.375 85.457,22.375 92.23,15.602 J500.6@92.23,9.67
SYS_JTDI: J500.10 STM400.77 | length 34.2
  Top Layer w0.3: STM400.77@76.25,31.025 76.25,25.272 78.722,22.8 85.633,22.8 94.77,13.663 J500.10@94.77,8.535
SYS_JTDO_SWO: J500.8 STM400.89 | length 35.7
  Top Layer w0.3: STM400.89@82.25,31.025 82.25,29.749 83.499,28.5 84.296,28.5 87.021,25.775 96.475,25.775 v1(96.5,25.8) ; J500.8@93.5,8.535 v1(93.5,10.8)
  Bottom Layer w0.3: v1(93.5,10.8) 96.5,13.8 v1(96.5,25.8)
SYS_JTMS_SWDIO: J500.4 STM400.72 | length 37.3
  Top Layer w0.3: STM400.72@74.025,34.25 74.85,34.25 75.1,34 75.1,25.219 78.37,21.95 85.281,21.95 90.96,16.271 J500.4@90.96,8.535
SYS_JTRST: J500.12 STM400.90 | length 34.5
  Top Layer w0.3: STM400.90@82.75,31.025 82.75,29.85 83.6,29 84.397,29 87.022,26.375 97.175,26.375 v1(97.2,26.4) ; v1(96,10.8) 96.02,10.78 96.02,9.68 J500.12@96.1,9.6
  Bottom Layer w0.3: v1(96,10.8) 96,11.5 97.25,12.75 97.25,26.35 v1(97.2,26.4)
TypeB: M701.3 U600.3 | length 76.8
  Top Layer w0.2: U600.3@100.35,79.53 100.35,79.365 100.515,79.365 100.8,79.08 v1(100.8,78.4)
  Top Layer w0.25: M701.3@36.95,51.846 M701.3@36.996,51.8 ; M701.3@36.996,51.75 v1@70.5,51.75 ; v1(88.9,69.5) v1(91.7,69.5)
  Bottom Layer w0.25: v1(70.5,51.8) 70.567,51.867 71.267,51.867 v1(88.9,69.5) ; v1(91.7,69.5) 91.767,69.567 92.767,69.567 100.8,77.6 v1(100.8,78.4)
Ucenter: L702.1 L704.2 L704.3 | length 5
  Top Layer w1: L704.2@42.95,78.71 L704.3@42.95,81.25 ; L704.3@43.75,81.25 L702.1@46.25,81.25
Upeak: C703.1 C704.1 D702.1 D703.1 D704.1 R703.1 R705.1 | length 29.6
  Top Layer w0.6: D704.1@59.9,73.452 C704.1@62.25,73.452 R705.1@64.75,73.452 66.5,73.452 66.552,73.4 67.9,73.4 74.5,66.8 R703.1@74.5,64.752
  Top Layer w0.8: v1(59.75,74.5) 59.75,73.49 59.805,73.435 D704.1@59.9,73.435 ; D703.1@59.75,80.135 v1(59.75,81.25) D702.1@59.75,82.365
  Bottom Layer w0.8: v1(59.75,74.5) v1(59.75,81.25)
V_CNTR: R304.1 STM400.29 | length 57.2
  Top Layer w0.3: STM400.29@86.25,46.475 86.25,44.55 v1(86.3,44.5)
  Bottom Layer w0.3: R304.1@38.65,26.2 55.8,26.2 72.8,43.2 85,43.2 v1(86.3,44.5)
V_POWER: C301.2 R300.1 R301.2 STM400.16 | length 61
  Top Layer w0.3: v1(76.4,44.6) 80.75,40.25 STM400.16@89.475,40.25
  Bottom Layer w0.3: C301.2@35.5,44 36.6,45.1 75.839,45.1 76.339,44.6 v1(76.4,44.6)
  Bottom Layer w1.1: R300.1@30.65,44 R301.2@33,44 C301.2@35.25,44
VDD: C626.1 C627.1 J610.2 J611.1 R609.1 U601.8 | length 5.8
  Top Layer w0.25: U601.8@86,84.5 86,85.363 86.357,85.721 C626.1@86.357,85.8
  Top Layer w0.4: C626.1@86.357,85.8 C627.1@86.357,87 R609.1@86.357,88.2
  Top Layer w0.5: J610.2@85.6,89.2 85.737,89.2 85.945,88.993 86.502,88.993 86.6,88.895 86.6,88.422 86.378,88.2 R609.1@86.357,88.2
VDD_A: C623.1 C624.1 U601.7 | length 2.9
  Top Layer w0.25: U601.7@86.5,84.5 86.5,84.78 86.845,85.125 86.847,85.125 87.443,85.721 C623.1@87.443,85.8
  Top Layer w0.4: C623.1@87.443,85.8 C624.1@87.443,87
VDD_AM: C608.1 C609.1 U601.11 | length 4.8
  Top Layer w0.25: C609.1@83.657,86.5 83.807,86.35 83.807,84.15 C608.1@83.757,84.1 ; C608.1@83.832,84.1 83.832,83.582 84.5,82.914 84.5,82.9 84.65,82.75 U601.11@85.25,82.75
VDD_D: C621.1 C622.1 U601.3 | length 2.8
  Top Layer w0.15: U601.3@88.525,84.803 C621.1@89.443,85.721
  Top Layer w0.2: U601.3@88.5,84.5 U601.3@88.5,84.764 ; C621.1@89.443,85.721 C621.1@89.443,85.8
  Top Layer w0.4: C621.1@89.443,85.8 C622.1@89.443,87
VDD_RF: C610.1 C611.1 C619.1 C620.1 J610.1 U601.9 U601.14 | length 10.1
  Top Layer w0.25: v3(84.55,81.25) U601.14@85.25,81.25 ; v3(84.857,84.15) 84.905,84.102 84.905,83.845 85,83.75 U601.9@85.25,83.75
  Top Layer w0.5: v3(83.4,81.25) v3(83.975,81.25) v3(84.55,81.25) ; v3(84.6,88.5) J610.1@84.6,89.2
  Bottom Layer w0.5: v3(84.6,88.5) 84.85,88.25 84.85,85.15 84.85,84.707 C620.1@84.843,84.7 84.843,84.164 v3(84.857,84.15) 84.843,84.136 C619.1@84.843,83.1 C610.1@84.843,81.8
  other v3: 84.9,85.1
VDD_TX: C612.1 C613.1 R609.2 U601.10 | length 6.4
  Top Layer w0.25: C612.1@84.257,85.3 C612.1@84.332,85.225 ; C612.1@84.332,85.221 84.257,85.146 84.257,83.843 84.85,83.25 U601.10@85.25,83.25 ; R609.2@85.443,88.121 R609.2@85.443,88.2
  Top Layer w0.4: C612.1@84.257,85.3 C613.1@84.257,87.521 ; C613.1@84.257,87.7 85.022,87.7 R609.2@85.443,88.121
VDDA: C405.1 C407.1 L400.1 R409.1 STM400.22 | length 12.6
  Top Layer w0.3: STM400.22@89.475,43.25 92.217,43.25 R409.1@93.7,44.733
  Top Layer w0.6: L400.1@90.486,48.467 C407.1@91.8,48.467 93.154,48.467 C405.1@93.7,49.012 v1(93.7,47.7) ; R409.1@93.7,44.733 v1(93.7,45.5)
  Bottom Layer w0.6: v1(93.7,45.5) v1(93.7,47.7)
Version_GPIO_1: J400.2 STM400.84 | length 4.3
  Top Layer w0.3: STM400.84@79.75,31.025 79.75,28.05 80.1,27.7 J400.2@80.1,26.882
Version_GPIO_2: J401.2 STM400.85 | length 4.7
  Top Layer w0.3: STM400.85@80.25,31.025 80.25,28.65 81.475,27.425 81.475,27.107 J401.2@81.7,26.882
Version_GPIO_3: J402.2 STM400.86 | length 5.2
  Top Layer w0.3: STM400.86@80.75,31.025 80.75,29.446 83.021,27.175 83.032,27.175 83.097,27.11 J402.2@83.356,27.11
Von: C300.1 C701.1 C702.1 D700.1 JP300.1 JP300.3 M700.2 P700.3 R300.2 R700.1 R701.1 T700.4 U700.5 | length 20.6
  Top Layer w1.1: T700.4@28.25,61.5 T700.4@29,60.75
  Top Layer w1.4: U700.5@22.8,59.5 22.8,60.3 24,61.5 T700.4@28.25,61.5 ; T700.4@29,60.75 29.684,61.434 D700.1@33.451,61.434 ; D700.1@33.537,61.422 37.753,61.422 M700.2@37.8,61.375
  Bottom Layer w1.1: JP300.1@26.29,41.25 28.75,43.71 R300.2@28.75,44
  other v2: 13,58 14,58 15,58 13,59 14,59 15,59 13,60 14,60 15,60
VREF+: C404.1 C406.1 R409.2 STM400.21 | length 6.9
  Top Layer w0.3: STM400.21@89.475,42.75 91.183,42.75 C404.1@91.8,42.133
  Top Layer w0.6: C404.1@91.8,42.133 93.111,42.133 C406.1@93.7,41.544 ; C406.1@93.7,41.5 C406.1@93.7,41.544 ; R409.2@93.7,43.667 C406.1@93.7,41.544
Vreg: C303.2 C304.2 JP300.2 L300.2 R303.2 TP306.1 | length 11
  Top Layer w0.6: R303.2@28,34.45 38.6,34.45 L300.2@38.9,34.15
pads on no net: "Power in300.2" BootL400.0 BootL400.3 BootL400.4 H1.1 H2.1 H3.1 H4.1 H5.1 H6.1 J500. J500.1 J500.2 J500.9 J500.11 L704.5 L704.6 M701.1 M701.2 M701.6 P500.1 P500.3 P500.5 P500.7 P501.3 P700.1 Reset400.0 Reset400.3 Reset400.4 STM400.1 STM400.2 STM400.4 STM400.5 STM400.6 STM400.12 STM400.13 STM400.18 STM400.26 STM400.34 STM400.35 STM400.36 STM400.37 STM400.38 STM400.39 STM400.41 STM400.42 STM400.43 STM400.45 STM400.46 STM400.47 STM400.48 STM400.51 STM400.52 STM400.53 STM400.54 STM400.55 STM400.56 STM400.57 STM400.60 STM400.61 STM400.62 STM400.64 STM400.66 STM400.67 STM400.70 STM400.71 STM400.74 STM400.81 STM400.91 STM400.95 T700.2 U601.28

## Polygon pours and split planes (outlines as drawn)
5V on PWR "PWR_5V" (solid, remove dead copper, pour order 489): 2,98 108,98 108,2 2,2
NetC700_1 on PWR "PWR_NETC700_1" (solid, remove dead copper, pour order 487): 2,98 56,98 56,56.7 54,56.7 46.589,64.111 1.89,64.111
GND on PWR "PWR_GND" (solid, pour order 490): 0,1.27 0,98.73 cw(c1.27,98.73) 1.27,100 108.73,100 cw(c108.73,98.73) 110,98.73 110,1.27 cw(c108.73,1.27) 108.73,0 1.27,0 cw(c1.27,1.27)
24V on PWR "PWR_24V" (solid, pour order 486): 39.75,30.743 53.503,30.743 53.503,2.003 53.5,2 25,2 2,2 2,37.69 2.007,37.697 2,40 39.75,40
Von on PWR "PWR_Von" (solid, remove dead copper, pour order 485): 46.5,64 53.75,56.75 53.75,40.25 2,40.25 2,64
3V3 on PWR "PWR_3V3" (solid, pour order 488): 89,98 108,98 108,2 107.984,2.016 65.516,2.016 65.511,2.011 65.511,17.511 71,23 71,45 89,63
GND on Top Layer "Top_GND" (solid, pour order 483): 0,1.27 0,98.73 cw(c1.27,98.73) 1.27,100 108.73,100 cw(c108.73,98.73) 110,98.73 110,1.27 cw(c108.73,1.27) 108.73,0 1.27,0 cw(c1.27,1.27)
NetD300_2 on Top Layer "NETD300_2_L01_P479" (solid, pour order 479): 26.5,26.5 26.5,24.9 27.6,24.9 27.9,24.6 27.9,21.6 28,21.5 40.8,21.5 40.8,26.5
NetC302_2 on Top Layer "Top_NetC302_2" (solid, pour order 476): 25.7,21.6 22.9,21.6 20.25,24.25 20.25,28.25 21.5,28.25 21.5,27.5 22.5,26.5 25.7,26.5
Vreg on Top Layer "Top_Vreg" (solid, pour order 481): 36.75,36.5 37.75,35.5 40.8,35.5 40.8,32.6 32.5,32.6 32.5,37.25 25,37.25 25,40 27.75,40 29,41.25 36.75,41.25
5V on Top Layer "Top_5V" (solid, pour order 474): 56.5,12.65 66.25,12.65 66.25,11.15 59.75,11.15 59.5,10.9 59.5,9.75 56.5,9.75
5V on Top Layer "Top_5V" (solid, pour order 482): 32.25,18 32.75,18.5 55.75,18.5 57.5,16.75 57.5,14.094 57.156,13.75 32.75,13.75 32.25,14.25
NetC310_1 on Top Layer "Top_NetC310_1" (solid, pour order 480): 39.25,4 38.75,3.5 21.5,3.5 20.25,4.75 20.25,8.75 21.5,8.75 21.5,8 22.75,6.75 32.25,6.75 32.75,7.25 38.75,7.25 39.25,6.75
Von on Top Layer "Top_Von" (solid, pour order 475): 12.5,60.4 23.5,60.4 23.5,58.9 15.75,58.9 15.5,58.65 15.5,57.5 12.5,57.5
3V3 on Top Layer "Top_3V3" (solid, pour order 473): 79.5,12.65 69.75,12.65 69.75,11.15 76.25,11.15 76.5,10.9 76.5,9.75 79.5,9.75
24V on Top Layer "Top_24V_2" (solid, pour order 477): 7.4,8.944 8.044,8.3 14.3,8.3 15.1,9.1 15.1,10.1 14.2,11 14.2,11.8 13.5,12.5 8,12.5 7.4,11.9
24V on Top Layer "Top_24V" (solid, pour order 478): 7.4,28.444 8.044,27.8 14.3,27.8 15.1,28.6 15.1,29.6 14.2,30.5 14.2,31.3 13.5,32 8,32 7.4,31.4
GND on GND "GND_GND" (solid, pour order 484): 0,1.27 0,98.73 cw(c1.27,98.73) 1.27,100 108.73,100 cw(c108.73,98.73) 110,98.73 110,1.27 cw(c108.73,1.27) 108.73,0 1.27,0 cw(c1.27,1.27)
GND on Bottom Layer "Bottom_GND" (solid, pour order 491): 0,1.27 0,98.73 cw(c1.27,98.73) 1.27,100 108.73,100 cw(c108.73,98.73) 110,98.73 110,1.27 cw(c108.73,1.27) 108.73,0 1.27,0 cw(c1.27,1.27)

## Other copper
Bottom Layer:
  region net VDD_RF: 85.025,80.35 85.025,82.15 84.525,82.15 83.9,81.525 83.3,81.525 83.15,81.375 83.15,81.125 83.3,80.975 83.9,80.975 84.525,80.35

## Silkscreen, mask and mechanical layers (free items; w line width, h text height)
Top Overlay:
  drawing of 25 lines, arcs and shapes, not listed
  text "FOD_Res" at 65.25,95.5 h0.6 r90
  text "FOD_WU" at 66.25,95.5 h0.6 r90
  text "COM_Sl" at 67.25,95.5 h0.6 r90
  text "IGPT" at 68.25,95.5 h0.6 r90
  text "24V" at 61.25,90.5 h0.6 r90
  text "--" at 62.25,90.5 h0.6 r90
  text "5V" at 63.25,90.5 h0.6 r90
  text "3V3" at 64.25,90.5 h0.6 r90
  text "FOD_RX" at 65.25,90.5 h0.6 r90
  text "FOD_TX" at 66.25,90.5 h0.6 r90
  text "FOD_Rea" at 67.25,90.5 h0.6 r90
  text "FOD_Slot" at 68.25,90.5 h0.6 r90
  text "FOR EVALUATION ONLY / NOT FCC APPROVED / FOR RESALE" at 1.5,53.75 h2 r270
  text "WARNING!" at 57.563,50.909 h2
  text "HIGH VOLTAGE" at 56.215,49.223 h1.8
  text "ON BOARD" at 57.935,47.723 h1.8
  text "Von" at 24,42.75 h0.8
  text "FOD_ADC" at 98.9,41.2 h0.6
  text "DAC_OUT" at 98.9,40.1 h0.6
  text "FOD_PWM" at 98.9,38.5 h0.6
  text "Vreg" at 30.2,38.45 h0.8 r90
  text "24V" at 21.5,38 h0.8 r90
  text "Spare_PWM" at 97.7,37.4 h0.6
  text "Vreg" at 31.3,36.2 h0.8
  text "Spare_GPIO" at 97.2,35.7 h0.6
  text "24V" at 101.2,29.5 h0.6
  text "+" at 2.95,27.05 h2
  text "16V" at 101.3,26.9 h0.6
  text "5V" at 101.2,25 h0.6
  text "3V3" at 101.2,23.6 h0.6
  text "NFC_Re" at 95,21.5 h0.6
  text "NFC_RX" at 95,18.7 h0.6
  text "5V" at 54.4,18 h0.8
  text "24V" at 9.1,17.6 h0.8
  text "3V3" at 73,16.6 h0.8
  text "NFC_TX" at 95,16.1 h0.6
  text "NFC_WU" at 97.7,14.7 h0.6
  text "NFC_Ready" at 97.7,13.7 h0.6
  text "COM" at 100.8,12.7 h0.6
  text "-" at 5.45,11.8 h2 r90
  text "FOD" at 100.8,11.7 h0.6
  text "IGBT" at 100.7,10.7 h0.6
  text "STEVAL-KiTXCBN / STEVAL$KiTXCBNA" at 63.2,2.1 h2.6
  text "J" at 45.86,0.576 h15.24
1 Board outline:
  lines w0.254: 0,1.27 ccw(c1.27,1.27) 1.27,0 108.73,0 ccw(c108.73,1.27) 110,1.27 110,98.73 ccw(c108.73,98.73) 108.73,100 1.27,100 ccw(c1.27,98.73) 0,98.73 0,3 0,1.27
3 3D Body outline top:
  circle w0.25: c4,96 r3
  circle w0.25: c106,96 r3
  circle w0.25: c106,4 r3
  circle w0.25: c4.025,4 r3

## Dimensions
107,12 to 107,14.54 on 11 Dimensions board
106,96 to 92,96.995 on 11 Dimensions board
106,96 to 92,96.995 on 11 Dimensions board
106,96 to 108.73,100 on 11 Dimensions board
106,96 to 110,98.73 on 11 Dimensions board
106,96 to 106,60 on 11 Dimensions board
106,4 to 107,12 on 11 Dimensions board
106,4 to 107,36 on 11 Dimensions board
106,4 to 107,12 on 11 Dimensions board
4,4 to 1.27,0 on 11 Dimensions board
4,4 to 0,1.27 on 11 Dimensions board
106,4 to 4,4 on 11 Dimensions board
0,1.27 to 110,1.27 on 11 Dimensions board
4,96 to 4,4 on 11 Dimensions board
1.27,0 to 1.27,100 on 11 Dimensions board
